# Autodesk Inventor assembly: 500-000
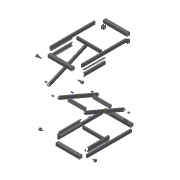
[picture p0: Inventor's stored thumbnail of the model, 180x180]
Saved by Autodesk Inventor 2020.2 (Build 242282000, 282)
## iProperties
Created: 2016-09
Part Number: 500-000
Document SubType Name: Assembly
Designer: F.Stasiak
Manager: www.cadconsulting.pl
Company: Fabian Stasiak CAD Consulting
Author: F.Stasiak
Subject: Zbiór ćwiczeń. Autodesk Inventor 2020. Kurs podstawowy
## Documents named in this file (14)
- C:\2020_Kurs_podstawowy\R6 Zespoły\Warsztat\500-000.iam
- C:\2020_Kurs_podstawowy\R6 Zespoły\Warsztat\Komponenty\500-01-06.ipt
- C:\2020_Kurs_podstawowy\R6 Zespoły\Warsztat\Komponenty\500-01-07.ipt
- C:\2020_Kurs_podstawowy\R6 Zespoły\Warsztat\Komponenty\EN 10058 - 500-01-08.ipt
- C:\2020_Kurs_podstawowy\R6 Zespoły\Warsztat\Komponenty\DIN 120x60x4 500-01-01.ipt
- C:\2020_Kurs_podstawowy\R6 Zespoły\Warsztat\Komponenty\DIN 120x60x4 500-01-02.ipt
- C:\2020_Kurs_podstawowy\R6 Zespoły\Warsztat\Komponenty\DIN 120x60x4 500-01-04.ipt
- C:\2020_Kurs_podstawowy\R6 Zespoły\Warsztat\Komponenty\DIN 59 410 - 500-03-04.ipt
- C:\2020_Kurs_podstawowy\R6 Zespoły\Warsztat\Komponenty\500-03-02.ipt
- C:\2020_Kurs_podstawowy\R6 Zespoły\Warsztat\Komponenty\DIN 59 410 - 500-03-03.ipt
- C:\2020_Kurs_podstawowy\R6 Zespoły\Warsztat\Komponenty\DIN 59 410 - 500-04-01.ipt
- C:\2020_Kurs_podstawowy\R6 Zespoły\Warsztat\Komponenty\500-05-01.ipt
- C:\2020_Kurs_podstawowy\R6 Zespoły\Warsztat\Komponenty\500-06-01.ipt
- C:\2020_Kurs_podstawowy\R6 Zespoły\Warsztat\Komponenty\500-01-08.ipt
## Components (46 placed, 13 different names)
1. DIN 120x60x4 500-01-01:1
2. DIN 120x60x4 500-01-02:1
3. DIN 120x60x4 500-01-04:1
4. DIN 120x60x4 500-01-01:2 — Zestawiający:1
5. DIN 120x60x4 500-01-04:2
6. 500-01-07:1
7. 500-01-07:2
8. 500-01-07:3
9. 500-01-07:4
10. EN 10058 - 500-01-08:1
11. EN 10058 - 500-01-08:2
12. 500-01-06:1
13. 500-01-06:2
14. 500-01-08:2
15. 500-01-08:1
16. DIN 59 410 - 500-03-04:1
17. DIN 59 410 - 500-03-04:2
18. DIN 59 410 - 500-03-03:1
19. DIN 59 410 - 500-03-03:2
20. 500-03-02:1
21. 500-03-02:2
22. 500-03-02:3
23. 500-03-02:4
24. 500-03-02:5
25. 500-03-02:6
26. DIN 59 410 - 500-04-01:1
27. 500-03-02:7
28. 500-03-02:8
29. 500-03-02:9
30. DIN 120x60x4 500-01-01:3
31. DIN 120x60x4 500-01-01:4
32. DIN 120x60x4 500-01-04:3
33. DIN 120x60x4 500-01-04:4
34. DIN 120x60x4 500-01-02:2
35. 500-01-07:5
36. 500-01-07:6
37. 500-01-07:7
38. 500-01-07:8
39. EN 10058 - 500-01-08:3
40. EN 10058 - 500-01-08:4
41. 500-01-06:3
42. 500-01-06:4
43. 500-05-01:1
44. 500-05-01:2
45. 500-06-01:1
46. 500-06-01:2
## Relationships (1: Mate 1)
- Zestawiający:1 [Mate]: DIN 120x60x4 500-01-01:2
